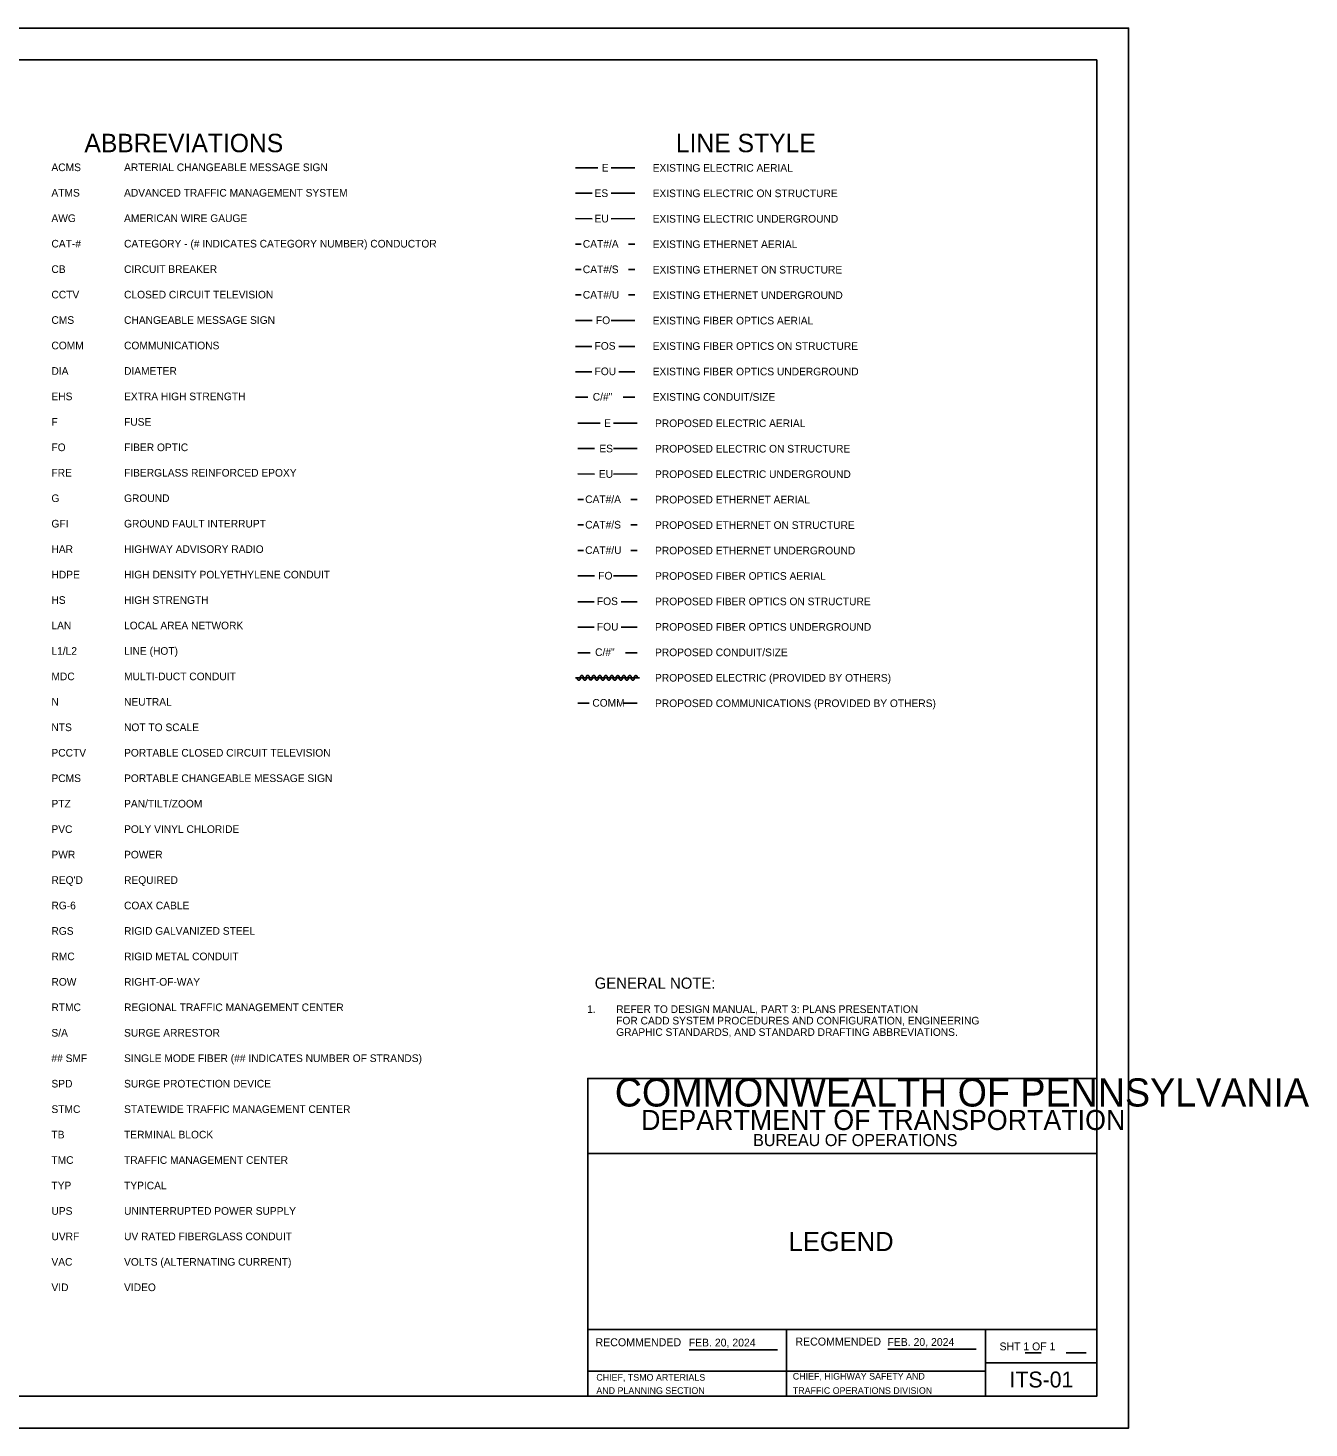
# Model space of a CAD drawing. Extents: x 1299104.8 to 1299141.6, y 239639.8 to 239661.8.
# Drawn here: x 1299121.51 to 1299141.64, y 239639.79 to 239661.79 of the extents above; entities that cross this region are included whole.
import ezdxf

# ---------------------------------------------------------------- set-up
doc = ezdxf.new("R2010")
doc.units = 0
for name, color, linetype in [('1', 7, 'Continuous'), ('2', 7, 'Continuous'), ('DIM TXT', 7, 'Continuous'), ('GS_noplot_1', 7, 'Continuous'), ('Level 1', 7, 'Continuous'), ('PDF3_Geometry', 7, 'Continuous'), ('PDF4_Geometry', 7, 'Continuous'), ('PDF_LEGEND', 7, 'Continuous'), ('PTEXT', 7, 'Continuous')]:
    doc.layers.add(name, color=color, linetype=linetype)

msp = doc.modelspace()

# ---------------------------------------------------------------- linework, layer by layer
at = {"layer": '1'}
for p, q in [((1299131.894, 239641.02), (1299133.284, 239641.02)), ((1299135.016, 239641.029), (1299136.405, 239641.029)), ((1299137.176, 239640.973), (1299137.427, 239640.973)), ((1299137.819, 239640.973), (1299138.133, 239640.973)), ((1299130.302, 239640.682), (1299133.427, 239640.682))]:
    msp.add_line(p, q, dxfattribs=at)
at = {"layer": 'GS_noplot_1'}
for points in [[(1299104.802, 239661.791), (1299138.802, 239661.791), (1299138.802, 239639.791), (1299104.802, 239639.791)], [(1299130.302, 239641.339), (1299136.552, 239641.339), (1299136.552, 239640.291), (1299130.302, 239640.291)]]:
    msp.add_lwpolyline(points, close=True, dxfattribs=at)
at = {"layer": 'Level 1'}
for p, q in [((1299130.302, 239641.339), (1299138.302, 239641.339)), ((1299133.427, 239641.339), (1299133.427, 239640.291)), ((1299136.552, 239640.815), (1299138.302, 239640.815)), ((1299133.427, 239640.682), (1299136.552, 239640.682))]:
    msp.add_line(p, q, dxfattribs=at)
for points in [[(1299138.302, 239640.291), (1299106.302, 239640.291), (1299106.302, 239661.291), (1299138.302, 239661.291)], [(1299138.302, 239645.284), (1299130.302, 239645.284), (1299130.302, 239644.104), (1299138.302, 239644.104)], [(1299138.302, 239645.284), (1299130.302, 239645.284), (1299130.302, 239640.291), (1299138.302, 239640.291)]]:
    msp.add_lwpolyline(points, close=True, dxfattribs=at)
at = {"layer": 'PDF3_Geometry'}
msp.add_lwpolyline([(1299130.108, 239651.58), (1299131.116, 239651.58)], dxfattribs=at)
for points in [[(1299130.138, 239651.58), (1299130.138, 239651.561), (1299130.148, 239651.544), (1299130.162, 239651.544)], [(1299130.162, 239651.544), (1299130.175, 239651.544), (1299130.186, 239651.561), (1299130.186, 239651.58)], [(1299130.21, 239651.615), (1299130.196, 239651.615), (1299130.186, 239651.599), (1299130.186, 239651.579)], [(1299130.232, 239651.579), (1299130.232, 239651.599), (1299130.222, 239651.615), (1299130.21, 239651.615)], [(1299130.232, 239651.579), (1299130.232, 239651.56), (1299130.243, 239651.544), (1299130.256, 239651.544)], [(1299130.256, 239651.544), (1299130.27, 239651.544), (1299130.279, 239651.56), (1299130.279, 239651.579)], [(1299130.303, 239651.617), (1299130.29, 239651.617), (1299130.279, 239651.6), (1299130.279, 239651.58)], [(1299130.327, 239651.58), (1299130.327, 239651.6), (1299130.317, 239651.617), (1299130.303, 239651.617)], [(1299130.327, 239651.58), (1299130.327, 239651.561), (1299130.338, 239651.546), (1299130.35, 239651.546)], [(1299130.35, 239651.546), (1299130.363, 239651.546), (1299130.374, 239651.561), (1299130.374, 239651.58)], [(1299130.398, 239651.615), (1299130.384, 239651.615), (1299130.374, 239651.6), (1299130.374, 239651.58)], [(1299130.422, 239651.58), (1299130.422, 239651.6), (1299130.41, 239651.615), (1299130.398, 239651.615)], [(1299130.422, 239651.58), (1299130.422, 239651.561), (1299130.431, 239651.544), (1299130.445, 239651.544)], [(1299130.445, 239651.544), (1299130.458, 239651.544), (1299130.468, 239651.561), (1299130.468, 239651.58)], [(1299130.491, 239651.615), (1299130.479, 239651.615), (1299130.468, 239651.599), (1299130.468, 239651.579)], [(1299130.515, 239651.579), (1299130.515, 239651.599), (1299130.505, 239651.615), (1299130.491, 239651.615)], [(1299130.515, 239651.58), (1299130.515, 239651.561), (1299130.526, 239651.544), (1299130.539, 239651.544)], [(1299130.515, 239651.579), (1299130.515, 239651.56), (1299130.526, 239651.544), (1299130.539, 239651.544)], [(1299130.539, 239651.544), (1299130.551, 239651.544), (1299130.563, 239651.561), (1299130.563, 239651.58)], [(1299130.539, 239651.544), (1299130.551, 239651.544), (1299130.563, 239651.56), (1299130.563, 239651.579)], [(1299130.586, 239651.615), (1299130.574, 239651.615), (1299130.563, 239651.6), (1299130.563, 239651.58)], [(1299130.61, 239651.58), (1299130.61, 239651.6), (1299130.599, 239651.615), (1299130.586, 239651.615)], [(1299130.61, 239651.579), (1299130.61, 239651.56), (1299130.62, 239651.544), (1299130.634, 239651.544)], [(1299130.634, 239651.544), (1299130.646, 239651.544), (1299130.657, 239651.56), (1299130.657, 239651.579)], [(1299130.681, 239651.615), (1299130.667, 239651.615), (1299130.657, 239651.599), (1299130.657, 239651.579)], [(1299130.703, 239651.579), (1299130.705, 239651.599), (1299130.694, 239651.615), (1299130.681, 239651.615)], [(1299130.703, 239651.579), (1299130.703, 239651.56), (1299130.715, 239651.544), (1299130.727, 239651.544)], [(1299130.727, 239651.544), (1299130.741, 239651.544), (1299130.751, 239651.56), (1299130.751, 239651.579)], [(1299130.775, 239651.614), (1299130.762, 239651.614), (1299130.751, 239651.599), (1299130.751, 239651.579)], [(1299130.798, 239651.579), (1299130.798, 239651.599), (1299130.789, 239651.614), (1299130.775, 239651.614)], [(1299130.798, 239651.579), (1299130.798, 239651.56), (1299130.81, 239651.543), (1299130.822, 239651.543)], [(1299130.822, 239651.543), (1299130.835, 239651.543), (1299130.846, 239651.56), (1299130.846, 239651.579)], [(1299130.87, 239651.615), (1299130.856, 239651.615), (1299130.846, 239651.6), (1299130.846, 239651.58)], [(1299130.893, 239651.58), (1299130.893, 239651.6), (1299130.882, 239651.615), (1299130.87, 239651.615)], [(1299130.893, 239651.579), (1299130.893, 239651.56), (1299130.903, 239651.544), (1299130.916, 239651.544)], [(1299130.916, 239651.544), (1299130.93, 239651.544), (1299130.939, 239651.56), (1299130.939, 239651.579)], [(1299130.963, 239651.615), (1299130.95, 239651.615), (1299130.939, 239651.599), (1299130.939, 239651.579)], [(1299130.987, 239651.579), (1299130.987, 239651.599), (1299130.977, 239651.615), (1299130.963, 239651.615)], [(1299130.987, 239651.579), (1299130.987, 239651.56), (1299130.998, 239651.544), (1299131.01, 239651.544)], [(1299131.01, 239651.544), (1299131.023, 239651.544), (1299131.034, 239651.56), (1299131.034, 239651.579)], [(1299131.058, 239651.614), (1299131.045, 239651.614), (1299131.034, 239651.599), (1299131.034, 239651.579)], [(1299131.082, 239651.579), (1299131.082, 239651.599), (1299131.07, 239651.614), (1299131.058, 239651.614)]]:
    msp.add_open_spline(points, degree=2, dxfattribs=at)
at = {"layer": 'PDF4_Geometry'}
for points in [[(1299130.108, 239656.788), (1299130.367, 239656.788)], [(1299130.791, 239656.788), (1299131.042, 239656.788)], [(1299130.108, 239656.388), (1299130.367, 239656.388)], [(1299130.791, 239656.388), (1299131.042, 239656.388)], [(1299130.108, 239655.988), (1299130.304, 239655.988)], [(1299130.858, 239655.988), (1299131.042, 239655.988)], [(1299130.145, 239652.775), (1299130.404, 239652.775)], [(1299130.828, 239652.775), (1299131.079, 239652.775)], [(1299130.145, 239652.375), (1299130.404, 239652.375)], [(1299130.828, 239652.375), (1299131.079, 239652.375)], [(1299130.145, 239651.975), (1299130.341, 239651.975)], [(1299130.895, 239651.975), (1299131.079, 239651.975)]]:
    msp.add_lwpolyline(points, dxfattribs=at)
at = {"layer": 'PDF_LEGEND'}
for points in [[(1299130.108, 239659.596), (1299130.461, 239659.595)], [(1299131.042, 239659.596), (1299130.67, 239659.595)], [(1299130.108, 239659.196), (1299130.373, 239659.195)], [(1299131.042, 239659.196), (1299130.67, 239659.195)], [(1299130.108, 239658.796), (1299130.373, 239658.795)], [(1299131.042, 239658.796), (1299130.67, 239658.795)], [(1299130.108, 239658.396), (1299130.199, 239658.396)], [(1299131.042, 239658.396), (1299130.943, 239658.396)], [(1299130.108, 239657.996), (1299130.199, 239657.996)], [(1299131.042, 239657.996), (1299130.943, 239657.996)], [(1299130.108, 239657.596), (1299130.199, 239657.596)], [(1299131.042, 239657.596), (1299130.943, 239657.596)], [(1299130.108, 239657.196), (1299130.373, 239657.195)], [(1299131.042, 239657.196), (1299130.67, 239657.195)], [(1299130.145, 239655.583), (1299130.498, 239655.582)], [(1299131.079, 239655.583), (1299130.708, 239655.581)], [(1299130.145, 239655.183), (1299130.41, 239655.182)], [(1299131.079, 239655.183), (1299130.708, 239655.181)], [(1299130.145, 239654.783), (1299130.41, 239654.782)], [(1299131.079, 239654.783), (1299130.708, 239654.781)], [(1299130.145, 239654.383), (1299130.236, 239654.383)], [(1299131.079, 239654.383), (1299130.981, 239654.383)], [(1299130.145, 239653.983), (1299130.236, 239653.983)], [(1299131.079, 239653.983), (1299130.981, 239653.983)], [(1299130.145, 239653.583), (1299130.236, 239653.583)], [(1299131.079, 239653.583), (1299130.981, 239653.583)], [(1299130.145, 239653.183), (1299130.41, 239653.182)], [(1299131.079, 239653.183), (1299130.708, 239653.181)], [(1299130.145, 239651.183), (1299130.327, 239651.183)], [(1299131.079, 239651.183), (1299130.853, 239651.183)]]:
    msp.add_lwpolyline(points, dxfattribs=at)

# ---------------------------------------------------------------- texts
at = {"layer": '1'}
for s, height, p in [('COMMONWEALTH OF PENNSYLVANIA', 0.44223, (1299130.728, 239644.843)), ('DEPARTMENT OF TRANSPORTATION', 0.31514, (1299131.141, 239644.474)), ('BUREAU OF OPERATIONS', 0.18955, (1299132.901, 239644.221)), ('RECOMMENDED', 0.125, (1299130.424, 239641.076)), ('FEB. 20, 2024', 0.12303, (1299131.889, 239641.072)), ('RECOMMENDED', 0.125, (1299133.565, 239641.087)), ('FEB. 20, 2024', 0.12303, (1299135.011, 239641.081)), ('CHIEF, TSMO ARTERIALS ', 0.10417, (1299130.438, 239640.535)), ('CHIEF, HIGHWAY SAFETY AND ', 0.10417, (1299133.525, 239640.552)), ('AND PLANNING SECTION', 0.10417, (1299130.438, 239640.327)), ('TRAFFIC OPERATIONS DIVISION', 0.10417, (1299133.525, 239640.327))]:
    msp.add_text(s, height=height, dxfattribs=at).set_placement(p)
at = {"layer": '2'}
msp.add_text('SHT 1 OF 1', height=0.123, dxfattribs=at).set_placement((1299136.773, 239641.012))
at = {"layer": 'DIM TXT'}
for s, height, p in [('ABBREVIATIONS', 0.29, (1299122.394, 239659.839)), ('LINE STYLE', 0.29, (1299131.687, 239659.839)), ('ACMS', 0.12, (1299121.876, 239659.542)), ('EXISTING ELECTRIC AERIAL', 0.12, (1299131.323, 239659.533)), ('ATMS', 0.12, (1299121.876, 239659.142)), ('EXISTING ELECTRIC ON STRUCTURE', 0.12, (1299131.323, 239659.133)), ('AWG', 0.12, (1299121.876, 239658.742)), ('EXISTING ELECTRIC UNDERGROUND', 0.12, (1299131.323, 239658.733)), ('CAT-#', 0.12, (1299121.876, 239658.342)), ('EXISTING ETHERNET AERIAL', 0.12, (1299131.323, 239658.333)), ('CB', 0.12, (1299121.876, 239657.942)), ('EXISTING ETHERNET ON STRUCTURE', 0.12, (1299131.323, 239657.933)), ('CCTV', 0.12, (1299121.876, 239657.542)), ('EXISTING ETHERNET UNDERGROUND', 0.12, (1299131.323, 239657.533)), ('CMS', 0.12, (1299121.876, 239657.142)), ('EXISTING FIBER OPTICS AERIAL', 0.12, (1299131.323, 239657.133)), ('COMM', 0.12, (1299121.876, 239656.742)), ('EXISTING FIBER OPTICS ON STRUCTURE', 0.12, (1299131.323, 239656.733)), ('DIA', 0.12, (1299121.876, 239656.342)), ('EXISTING FIBER OPTICS UNDERGROUND', 0.12, (1299131.323, 239656.333)), ('EHS', 0.12, (1299121.876, 239655.942)), ('EXISTING CONDUIT/SIZE', 0.12, (1299131.323, 239655.933)), ('F', 0.12, (1299121.876, 239655.542)), ('PROPOSED ELECTRIC AERIAL', 0.12, (1299131.36, 239655.52)), ('FO', 0.12, (1299121.876, 239655.142)), ('PROPOSED ELECTRIC ON STRUCTURE', 0.12, (1299131.36, 239655.12)), ('FRE', 0.12, (1299121.876, 239654.742)), ('PROPOSED ELECTRIC UNDERGROUND', 0.12, (1299131.36, 239654.72)), ('G', 0.12, (1299121.876, 239654.342)), ('PROPOSED ETHERNET AERIAL', 0.12, (1299131.36, 239654.32)), ('GFI', 0.12, (1299121.876, 239653.942)), ('PROPOSED ETHERNET ON STRUCTURE', 0.12, (1299131.36, 239653.92)), ('HAR', 0.12, (1299121.876, 239653.542)), ('PROPOSED ETHERNET UNDERGROUND', 0.12, (1299131.36, 239653.52)), ('HDPE', 0.12, (1299121.876, 239653.142)), ('PROPOSED FIBER OPTICS AERIAL', 0.12, (1299131.36, 239653.12)), ('HS', 0.12, (1299121.876, 239652.742)), ('PROPOSED FIBER OPTICS ON STRUCTURE', 0.12, (1299131.36, 239652.72)), ('LAN', 0.12, (1299121.876, 239652.342)), ('PROPOSED FIBER OPTICS UNDERGROUND', 0.12, (1299131.36, 239652.32)), ('L1/L2', 0.12, (1299121.876, 239651.942)), ('PROPOSED CONDUIT/SIZE', 0.12, (1299131.36, 239651.92)), ('MDC', 0.12, (1299121.876, 239651.542)), ('PROPOSED ELECTRIC (PROVIDED BY OTHERS)', 0.12, (1299131.36, 239651.52)), ('N', 0.12, (1299121.876, 239651.142)), ('PROPOSED COMMUNICATIONS (PROVIDED BY OTHERS)', 0.12, (1299131.36, 239651.12)), ('NTS', 0.12, (1299121.876, 239650.742)), ('PCCTV', 0.12, (1299121.876, 239650.342)), ('PCMS', 0.12, (1299121.876, 239649.942)), ('PTZ', 0.12, (1299121.876, 239649.542)), ('PVC', 0.12, (1299121.876, 239649.142)), ('PWR', 0.12, (1299121.876, 239648.742)), ("REQ'D", 0.12, (1299121.876, 239648.342)), ('RG-6', 0.12, (1299121.876, 239647.942)), ('RGS', 0.12, (1299121.876, 239647.542)), ('RMC', 0.12, (1299121.876, 239647.142)), ('ROW', 0.12, (1299121.876, 239646.742)), ('GENERAL NOTE:', 0.175, (1299130.412, 239646.694)), ('RTMC', 0.12, (1299121.876, 239646.342)), (' 1.', 0.12, (1299130.25, 239646.313)), ('REFER TO DESIGN MANUAL, PART 3: PLANS PRESENTATION', 0.12, (1299130.75, 239646.313)), ('FOR CADD SYSTEM PROCEDURES AND CONFIGURATION, ENGINEERING ', 0.12, (1299130.75, 239646.133)), ('S/A', 0.12, (1299121.876, 239645.942)), ('GRAPHIC STANDARDS, AND STANDARD DRAFTING ABBREVIATIONS.', 0.12, (1299130.75, 239645.953)), ('## SMF', 0.12, (1299121.876, 239645.542)), ('SPD', 0.12, (1299121.876, 239645.142)), ('STMC', 0.12, (1299121.876, 239644.742)), ('TB', 0.12, (1299121.876, 239644.342)), ('TMC', 0.12, (1299121.876, 239643.942)), ('TYP', 0.12, (1299121.876, 239643.542)), ('UPS', 0.12, (1299121.876, 239643.142)), ('UVRF', 0.12, (1299121.876, 239642.742)), ('VAC', 0.12, (1299121.876, 239642.342)), ('VID', 0.12, (1299121.876, 239641.942))]:
    msp.add_text(s, height=height, dxfattribs=at).set_placement(p)
at = {"layer": 'PDF_LEGEND'}
for s, p in [('ARTERIAL CHANGEABLE MESSAGE SIGN', (1299123.017, 239659.542)), ('E', (1299130.523, 239659.536)), ('ADVANCED TRAFFIC MANAGEMENT SYSTEM', (1299123.017, 239659.142)), ('ES', (1299130.41, 239659.136)), ('AMERICAN WIRE GAUGE', (1299123.017, 239658.742)), ('EU', (1299130.41, 239658.736)), ('CATEGORY - (# INDICATES CATEGORY NUMBER) CONDUCTOR', (1299123.017, 239658.342)), ('CAT#/A', (1299130.226, 239658.339)), ('CIRCUIT BREAKER', (1299123.017, 239657.942)), ('CAT#/S', (1299130.226, 239657.939)), ('CLOSED CIRCUIT TELEVISION', (1299123.017, 239657.542)), ('CAT#/U', (1299130.226, 239657.539)), ('CHANGEABLE MESSAGE SIGN', (1299123.017, 239657.142)), ('FO', (1299130.432, 239657.138)), ('COMMUNICATIONS', (1299123.017, 239656.742)), ('FOS', (1299130.41, 239656.736)), ('DIAMETER', (1299123.017, 239656.342)), ('FOU', (1299130.41, 239656.336)), ('EXTRA HIGH STRENGTH', (1299123.017, 239655.942)), ('C/#"', (1299130.382, 239655.936)), ('FUSE', (1299123.017, 239655.542)), ('E', (1299130.56, 239655.523)), ('FIBER OPTIC', (1299123.017, 239655.142)), ('ES', (1299130.485, 239655.123)), ('FIBERGLASS REINFORCED EPOXY', (1299123.017, 239654.742)), ('EU', (1299130.478, 239654.723)), ('GROUND', (1299123.017, 239654.342)), ('CAT#/A', (1299130.263, 239654.326)), ('GROUND FAULT INTERRUPT', (1299123.017, 239653.942)), ('CAT#/S', (1299130.263, 239653.926)), ('HIGHWAY ADVISORY RADIO', (1299123.017, 239653.542)), ('CAT#/U', (1299130.263, 239653.526)), ('HIGH DENSITY POLYETHYLENE CONDUIT', (1299123.017, 239653.142)), ('FO', (1299130.469, 239653.125)), ('HIGH STRENGTH', (1299123.017, 239652.742)), ('FOS', (1299130.447, 239652.723)), ('LOCAL AREA NETWORK', (1299123.017, 239652.342)), ('FOU', (1299130.447, 239652.323)), ('LINE (HOT)', (1299123.017, 239651.942)), ('C/#"', (1299130.419, 239651.923)), ('MULTI-DUCT CONDUIT', (1299123.017, 239651.542)), ('NEUTRAL', (1299123.017, 239651.142)), ('COMM', (1299130.375, 239651.126)), ('NOT TO SCALE', (1299123.017, 239650.742)), ('PORTABLE CLOSED CIRCUIT TELEVISION', (1299123.017, 239650.342)), ('PORTABLE CHANGEABLE MESSAGE SIGN', (1299123.017, 239649.942)), ('PAN/TILT/ZOOM', (1299123.017, 239649.542)), ('POLY VINYL CHLORIDE', (1299123.017, 239649.142)), ('POWER', (1299123.017, 239648.742)), ('REQUIRED', (1299123.017, 239648.342)), ('COAX CABLE', (1299123.017, 239647.942)), ('RIGID GALVANIZED STEEL', (1299123.017, 239647.542)), ('RIGID METAL CONDUIT', (1299123.017, 239647.142)), ('RIGHT-OF-WAY', (1299123.017, 239646.742)), ('REGIONAL TRAFFIC MANAGEMENT CENTER', (1299123.017, 239646.342)), ('SURGE ARRESTOR', (1299123.017, 239645.942)), ('SINGLE MODE FIBER (## INDICATES NUMBER OF STRANDS)', (1299123.017, 239645.542)), ('SURGE PROTECTION DEVICE', (1299123.017, 239645.142)), ('STATEWIDE TRAFFIC MANAGEMENT CENTER', (1299123.017, 239644.742)), ('TERMINAL BLOCK', (1299123.017, 239644.342)), ('TRAFFIC MANAGEMENT CENTER', (1299123.017, 239643.942)), ('TYPICAL', (1299123.017, 239643.542)), ('UNINTERRUPTED POWER SUPPLY', (1299123.017, 239643.142)), ('UV RATED FIBERGLASS CONDUIT', (1299123.017, 239642.742)), ('VOLTS (ALTERNATING CURRENT)', (1299123.017, 239642.342)), ('VIDEO', (1299123.017, 239641.942))]:
    msp.add_text(s, height=0.12, dxfattribs=at).set_placement(p)
at = {"layer": 'PTEXT'}
for s, height, p in [('LEGEND', 0.3, (1299133.459, 239642.572)), ('ITS-01', 0.25, (1299136.93, 239640.428))]:
    msp.add_text(s, height=height, dxfattribs=at).set_placement(p)

doc.saveas('drawing.dxf')
